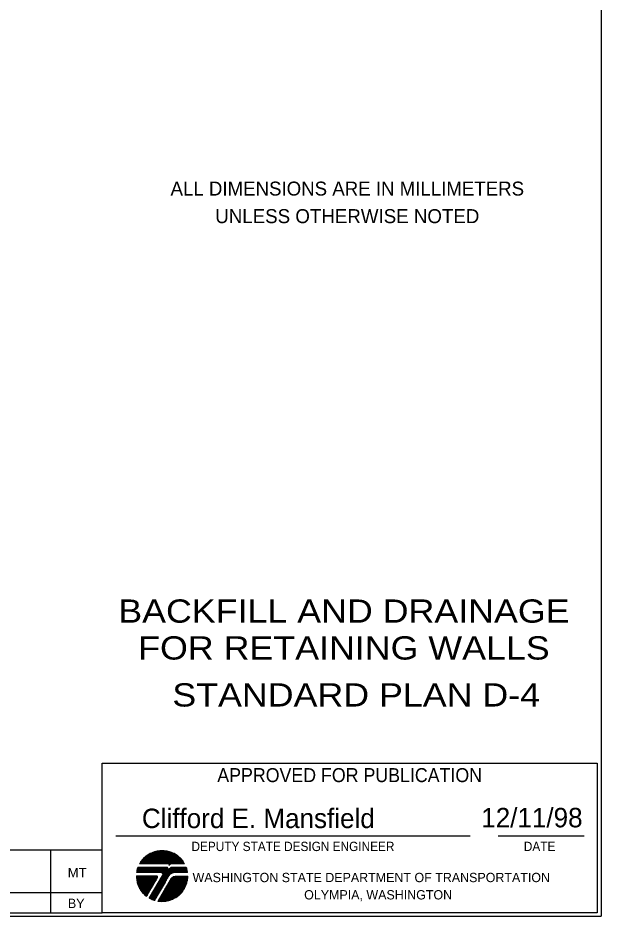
# Model space of a CAD drawing. Extents: x 17672 to 18472, y -9785 to -9267.
# Drawn here: x 18303.8 to 18471.8, y -9784.8 to -9525.9 of the extents above; entities that cross this region are included whole.
import ezdxf
from ezdxf.enums import TextEntityAlignment as Align

# ---------------------------------------------------------------- set-up
doc = ezdxf.new("R2010")
doc.units = 0
doc.header["$LTSCALE"] = 1.4
for name, color, linetype in [('19', 7, 'Continuous'), ('32', 7, 'Continuous'), ('62', 7, 'Continuous')]:
    doc.layers.add(name, color=color, linetype=linetype)
for name, color, linetype, lineweight in [('20', 7, 'Continuous', 25), ('30', 7, 'Continuous', 25), ('63', 7, 'Continuous', 13)]:
    doc.layers.add(name, color=color, linetype=linetype, lineweight=lineweight)

msp = doc.modelspace()

# ---------------------------------------------------------------- linework, layer by layer
at = {"layer": '20'}
for p, q in [((18328.054, -9740.702), (18470.641, -9740.702)), ((18331.951, -9761.602), (18434.072, -9761.602)), ((18442.143, -9761.602), (18466.95, -9761.602)), ((18313.274, -9783.872), (18313.274, -9765.673)), ((18328.054, -9783.872), (18328.054, -9765.673)), ((18175.947, -9777.972), (18328.054, -9777.972)), ((18175.947, -9783.872), (18328.054, -9783.872))]:
    msp.add_line(p, q, dxfattribs=at)
for points in [[(18470.641, -9740.702), (18470.641, -9783.872), (18328.054, -9783.872), (18328.054, -9740.702)], [(18175.947, -9783.872), (18175.947, -9765.673), (18328.054, -9765.673)]]:
    msp.add_lwpolyline(points, dxfattribs=at)
at = {"layer": '30'}
for p in [(18471.773, -9267.105), (17671.774, -9784.752)]:
    msp.add_line(p, (18471.773, -9784.752), dxfattribs=at)
at = {"layer": '63'}
for points in [[(18351.794, -9769.693), (18338.799, -9769.693), (18338.917, -9769.529), (18351.713, -9769.529), (18351.591, -9769.328), (18339.042, -9769.328), (18339.12, -9769.166), (18351.466, -9769.166), (18351.388, -9768.962), (18339.245, -9768.962), (18339.365, -9768.801), (18351.265, -9768.801), (18351.106, -9768.636), (18339.483, -9768.636), (18339.65, -9768.477), (18350.983, -9768.477), (18350.782, -9768.274), (18339.851, -9768.274), (18339.929, -9768.073), (18350.657, -9768.073), (18350.454, -9767.911), (18340.133, -9767.911), (18340.333, -9767.749), (18350.253, -9767.749), (18350.093, -9767.587), (18340.537, -9767.587), (18340.738, -9767.384), (18349.846, -9767.384), (18349.645, -9767.22), (18340.985, -9767.22), (18341.267, -9767.016), (18349.365, -9767.016), (18349.081, -9766.857), (18341.549, -9766.857), (18341.875, -9766.656), (18348.758, -9766.656), (18348.39, -9766.534), (18342.24, -9766.534), (18342.645, -9766.333), (18347.986, -9766.333), (18347.461, -9766.129), (18343.167, -9766.129), (18343.858, -9765.967), (18346.77, -9765.967), (18346.407, -9765.928), (18345.924, -9765.847), (18345.316, -9765.847), (18344.709, -9765.847), (18344.179, -9765.928), (18343.858, -9765.967)], [(18338.917, -9769.529), (18339.042, -9769.328), (18339.12, -9769.166), (18339.245, -9768.962), (18339.365, -9768.801), (18339.483, -9768.636), (18339.65, -9768.477), (18339.851, -9768.274), (18339.929, -9768.073), (18340.133, -9767.911), (18340.333, -9767.749), (18340.537, -9767.587), (18340.738, -9767.384), (18340.985, -9767.22), (18341.267, -9767.016), (18341.549, -9766.857), (18341.875, -9766.656), (18342.24, -9766.534), (18342.645, -9766.333), (18343.167, -9766.129)], [(18346.77, -9765.967), (18347.461, -9766.129), (18347.986, -9766.333), (18348.39, -9766.534), (18348.758, -9766.656), (18349.081, -9766.857), (18349.365, -9767.016), (18349.645, -9767.22), (18349.846, -9767.384), (18350.093, -9767.587), (18350.253, -9767.749), (18350.454, -9767.911), (18350.657, -9768.073), (18350.782, -9768.274), (18350.983, -9768.477), (18351.106, -9768.636), (18351.265, -9768.801), (18351.388, -9768.962), (18351.466, -9769.166), (18351.591, -9769.328), (18351.713, -9769.529), (18351.794, -9769.693)], [(18347.341, -9770.136), (18347.341, -9770.097), (18347.341, -9770.016), (18347.341, -9769.975), (18347.341, -9769.975), (18347.341, -9769.935), (18347.26, -9769.894), (18347.26, -9769.85), (18347.216, -9769.813), (18347.137, -9769.774), (18347.012, -9769.693)], [(18348.15, -9769.693), (18347.824, -9769.774), (18347.137, -9769.774), (18347.216, -9769.813), (18347.704, -9769.813), (18347.581, -9769.894), (18347.26, -9769.894), (18347.341, -9769.935), (18347.503, -9769.935), (18347.461, -9769.975), (18347.341, -9769.975), (18347.341, -9770.016), (18347.419, -9770.016), (18347.341, -9770.136), (18347.341, -9770.136), (18347.26, -9770.178), (18347.341, -9770.136)], [(18347.824, -9769.774), (18347.745, -9769.774), (18347.704, -9769.813), (18347.581, -9769.894), (18347.503, -9769.935), (18347.461, -9769.975), (18347.419, -9770.016)], [(18337.99, -9771.874), (18352.603, -9771.874), (18352.64, -9772.078), (18337.99, -9772.078), (18337.905, -9772.242), (18352.64, -9772.242), (18348.758, -9772.242), (18348.554, -9772.323), (18348.15, -9772.445), (18345.395, -9772.445), (18345.52, -9772.607), (18347.824, -9772.607), (18347.62, -9772.727), (18347.581, -9772.808), (18345.52, -9772.808), (18345.52, -9772.85), (18345.478, -9772.97), (18347.419, -9772.97), (18347.341, -9773.087), (18347.26, -9773.132), (18345.316, -9773.132), (18345.235, -9773.335), (18347.174, -9773.335), (18347.098, -9773.494), (18345.152, -9773.494), (18345.032, -9773.695), (18346.973, -9773.695), (18346.895, -9773.862), (18344.912, -9773.862), (18344.787, -9774.063), (18346.77, -9774.063), (18346.652, -9774.186), (18344.709, -9774.186), (18344.628, -9774.387), (18346.569, -9774.387), (18346.49, -9774.548), (18344.544, -9774.548), (18344.383, -9774.752), (18346.329, -9774.752), (18346.248, -9774.955), (18344.304, -9774.955), (18344.223, -9775.112), (18346.164, -9775.112), (18346.044, -9775.279), (18344.103, -9775.279), (18343.978, -9775.44), (18345.961, -9775.44), (18345.843, -9775.641), (18343.9, -9775.641), (18343.775, -9775.803), (18345.721, -9775.803), (18345.64, -9776.007), (18343.696, -9776.007), (18343.615, -9776.168), (18345.557, -9776.168), (18345.395, -9776.328), (18343.495, -9776.328), (18343.37, -9776.492), (18345.316, -9776.492), (18345.235, -9776.695), (18343.292, -9776.695), (18343.167, -9776.857), (18345.113, -9776.857), (18345.032, -9777.058), (18343.091, -9777.058), (18342.966, -9777.22), (18344.912, -9777.262), (18344.787, -9777.423), (18342.887, -9777.423), (18342.762, -9777.585), (18344.709, -9777.585), (18344.628, -9777.744), (18342.645, -9777.744), (18342.561, -9777.945), (18344.508, -9777.945), (18344.383, -9778.112), (18342.483, -9778.112), (18342.358, -9778.313), (18344.304, -9778.313), (18344.179, -9778.475), (18342.28, -9778.475), (18342.155, -9778.639), (18344.103, -9778.639), (18343.978, -9778.801), (18342.037, -9778.801), (18341.954, -9779.002), (18343.9, -9779.002), (18343.775, -9779.161), (18341.794, -9779.161), (18341.711, -9779.362), (18343.696, -9779.362), (18343.574, -9779.529), (18341.633, -9779.529), (18341.549, -9779.61), (18341.75, -9779.73), (18343.495, -9779.73), (18343.37, -9779.894), (18342.155, -9779.894), (18342.483, -9780.095), (18343.292, -9780.095), (18343.167, -9780.257)], [(18338.309, -9770.661), (18338.27, -9770.825), (18338.233, -9771.029), (18338.152, -9771.19), (18338.108, -9771.391), (18338.066, -9771.553), (18338.03, -9771.757), (18337.99, -9771.874), (18337.99, -9772.078)], [(18338.309, -9770.661), (18346.608, -9770.661), (18346.77, -9770.703), (18346.856, -9770.784), (18346.895, -9770.825), (18338.27, -9770.825), (18338.233, -9771.029), (18347.012, -9771.029), (18347.012, -9771.11), (18347.012, -9771.149), (18347.012, -9771.19), (18338.152, -9771.19), (18338.108, -9771.391), (18347.012, -9771.391), (18346.936, -9771.553), (18338.066, -9771.553), (18338.03, -9771.757), (18352.562, -9771.757), (18352.522, -9771.553), (18346.936, -9771.553), (18347.012, -9771.391), (18352.478, -9771.391), (18352.437, -9771.19), (18347.174, -9771.19), (18347.419, -9771.029), (18352.4, -9770.987), (18352.319, -9770.825), (18347.704, -9770.825), (18347.824, -9770.784), (18347.949, -9770.703), (18348.228, -9770.661), (18352.275, -9770.661), (18352.319, -9770.825)], [(18345.152, -9772.242), (18345.395, -9772.445), (18345.52, -9772.607), (18345.52, -9772.808), (18345.478, -9772.97), (18345.316, -9773.132), (18341.633, -9779.529), (18341.75, -9779.73), (18342.155, -9779.894)], [(18348.15, -9772.445), (18347.949, -9772.526), (18347.824, -9772.607), (18347.581, -9772.808), (18347.419, -9772.97), (18347.26, -9773.132), (18347.174, -9773.335), (18347.098, -9773.494), (18346.973, -9773.695), (18346.895, -9773.862), (18346.77, -9774.063), (18346.652, -9774.186), (18346.569, -9774.387), (18346.49, -9774.548), (18346.329, -9774.752), (18346.248, -9774.955), (18343.167, -9780.298)], [(18346.895, -9770.825), (18346.936, -9770.948), (18347.012, -9771.029), (18347.012, -9771.11), (18347.012, -9771.19), (18347.012, -9771.311), (18347.012, -9771.391)], [(18347.704, -9770.825), (18347.419, -9771.029), (18347.174, -9771.19), (18347.012, -9771.391)], [(18352.64, -9772.242), (18352.64, -9772.078), (18352.603, -9771.874), (18352.562, -9771.757), (18352.522, -9771.553), (18352.478, -9771.391), (18352.437, -9771.19), (18352.4, -9770.987)], [(18337.905, -9773.212), (18343.775, -9773.212), (18343.936, -9773.254), (18343.978, -9773.335), (18344.022, -9773.416), (18337.905, -9773.416), (18337.905, -9773.619), (18344.022, -9773.619), (18343.936, -9773.781), (18337.905, -9773.781), (18337.905, -9773.943), (18343.858, -9773.943), (18343.775, -9774.1), (18337.99, -9774.1), (18337.99, -9774.303), (18343.657, -9774.303), (18343.532, -9774.467), (18338.03, -9774.467), (18338.066, -9774.629), (18343.414, -9774.629), (18343.329, -9774.833), (18338.108, -9774.833), (18338.108, -9774.994), (18343.253, -9774.994), (18343.091, -9775.198), (18338.152, -9775.198), (18338.233, -9775.315), (18343.01, -9775.315), (18342.924, -9775.516), (18338.27, -9775.516), (18338.309, -9775.72), (18342.848, -9775.72), (18342.723, -9775.923), (18338.395, -9775.923), (18338.473, -9776.088), (18342.606, -9776.048), (18342.483, -9776.249), (18338.557, -9776.249), (18338.637, -9776.411), (18342.402, -9776.411), (18342.319, -9776.614), (18338.716, -9776.614), (18338.799, -9776.776), (18342.155, -9776.776), (18342.079, -9776.933), (18338.917, -9776.933), (18339.042, -9777.137), (18341.998, -9777.137), (18341.875, -9777.303), (18339.12, -9777.303), (18339.245, -9777.465), (18341.794, -9777.465), (18341.674, -9777.666), (18339.365, -9777.666), (18339.525, -9777.869), (18341.549, -9777.869), (18341.471, -9778.031), (18339.686, -9778.031), (18339.851, -9778.232), (18341.346, -9778.232), (18341.267, -9778.352), (18340.012, -9778.352), (18340.177, -9778.553), (18341.145, -9778.553), (18341.066, -9778.72), (18340.378, -9778.72), (18340.537, -9778.921), (18340.941, -9778.921), (18340.863, -9779.161), (18340.537, -9778.921)], [(18337.905, -9773.212), (18337.905, -9773.416), (18337.905, -9773.619), (18337.905, -9773.781), (18337.905, -9773.943), (18337.99, -9774.1), (18337.99, -9774.303), (18338.03, -9774.467), (18338.066, -9774.629), (18338.108, -9774.833), (18338.108, -9774.994), (18338.152, -9775.198), (18338.233, -9775.315), (18338.27, -9775.516), (18338.309, -9775.72), (18338.395, -9775.923), (18338.557, -9776.249), (18338.637, -9776.411), (18338.716, -9776.614), (18338.799, -9776.776), (18338.917, -9776.933), (18339.042, -9777.137), (18339.12, -9777.303), (18339.245, -9777.465), (18339.365, -9777.666), (18339.525, -9777.869), (18339.686, -9778.031), (18339.851, -9778.232), (18340.012, -9778.352), (18340.177, -9778.553), (18340.378, -9778.72), (18340.537, -9778.921), (18340.941, -9778.921), (18341.066, -9778.72), (18341.145, -9778.553), (18344.022, -9773.619), (18344.022, -9773.494), (18344.022, -9773.416)], [(18352.682, -9773.254), (18352.682, -9773.416), (18352.682, -9773.619), (18352.682, -9773.781), (18352.682, -9773.943), (18352.64, -9774.144), (18352.603, -9774.347), (18352.603, -9774.467), (18352.562, -9774.629), (18352.522, -9774.833), (18352.478, -9775.036), (18352.437, -9775.237), (18352.361, -9775.36), (18352.319, -9775.561), (18352.275, -9775.72), (18352.199, -9775.923), (18352.118, -9776.088), (18352.032, -9776.249), (18351.995, -9776.453), (18351.87, -9776.654), (18351.794, -9776.776), (18351.669, -9776.933), (18351.591, -9777.137), (18351.427, -9777.34), (18351.307, -9777.541), (18351.187, -9777.666), (18351.062, -9777.869), (18350.944, -9778.031), (18350.782, -9778.232), (18350.579, -9778.394), (18350.414, -9778.553), (18350.211, -9778.757), (18350.01, -9778.921), (18349.77, -9779.083), (18349.566, -9779.286), (18349.24, -9779.487), (18348.959, -9779.649), (18348.633, -9779.811), (18348.272, -9779.97), (18347.824, -9780.173), (18347.26, -9780.338), (18346.407, -9780.541), (18344.103, -9780.541), (18344.179, -9780.338), (18347.907, -9773.943), (18348.025, -9773.781), (18348.228, -9773.619), (18348.515, -9773.416)], [(18352.682, -9773.254), (18349.081, -9773.254), (18348.836, -9773.335), (18348.633, -9773.374), (18348.515, -9773.416), (18352.682, -9773.416), (18352.682, -9773.619), (18348.228, -9773.619), (18348.111, -9773.739), (18348.025, -9773.781), (18352.682, -9773.781), (18352.682, -9773.943), (18347.907, -9773.943), (18347.782, -9774.144), (18352.64, -9774.144), (18352.603, -9774.347), (18347.704, -9774.347), (18347.542, -9774.467), (18352.603, -9774.467), (18352.562, -9774.629), (18347.461, -9774.629), (18347.341, -9774.833), (18352.522, -9774.833), (18352.478, -9775.036), (18347.26, -9775.036), (18347.137, -9775.237), (18352.437, -9775.237), (18352.361, -9775.36), (18347.057, -9775.36), (18346.936, -9775.561), (18352.319, -9775.561), (18352.275, -9775.72), (18346.856, -9775.72), (18346.77, -9775.923), (18352.199, -9775.923), (18352.118, -9776.088), (18346.652, -9776.088), (18346.532, -9776.249), (18352.032, -9776.249), (18351.995, -9776.453), (18346.407, -9776.453), (18346.329, -9776.654), (18351.87, -9776.654), (18351.794, -9776.776), (18346.204, -9776.776), (18346.125, -9776.933), (18351.669, -9776.933), (18351.591, -9777.137), (18346, -9777.137), (18345.924, -9777.34), (18351.427, -9777.34), (18351.307, -9777.541), (18345.843, -9777.504), (18345.721, -9777.666), (18351.187, -9777.666), (18351.062, -9777.869), (18345.596, -9777.869), (18345.52, -9778.031), (18350.944, -9778.031), (18350.782, -9778.232), (18345.395, -9778.232), (18345.316, -9778.394), (18350.579, -9778.394), (18350.414, -9778.553), (18345.191, -9778.553), (18345.113, -9778.757), (18350.211, -9778.757), (18350.01, -9778.921), (18344.99, -9778.921), (18344.912, -9779.083), (18349.77, -9779.083), (18349.566, -9779.286), (18344.787, -9779.286), (18344.709, -9779.487)], [(18343.167, -9780.257), (18342.966, -9780.257), (18343.167, -9780.298), (18342.483, -9780.095)], [(18344.709, -9779.487), (18349.24, -9779.487), (18348.959, -9779.649), (18344.584, -9779.61), (18344.508, -9779.811), (18348.633, -9779.811), (18348.272, -9779.97), (18344.383, -9779.97), (18344.304, -9780.173), (18347.824, -9780.173), (18347.503, -9780.298), (18347.26, -9780.338), (18344.179, -9780.338), (18344.103, -9780.541), (18344.103, -9780.541), (18346.407, -9780.541), (18345.961, -9780.578), (18345.277, -9780.622), (18344.628, -9780.578), (18344.103, -9780.541)]]:
    msp.add_lwpolyline(points, dxfattribs=at)

# ---------------------------------------------------------------- texts
at = {"layer": '19'}
for s, height, p in [('ALL DIMENSIONS ARE IN MILLIMETERS', 4.02, (18398.674, -9577.108)), ('UNLESS OTHERWISE NOTED', 4.032, (18398.672, -9585.061))]:
    msp.add_text(s, height=height, dxfattribs=at).set_placement(p, align=Align.CENTER)
at = {"layer": '20'}
for s, height, width, p in [('APPROVED FOR PUBLICATION', 4.032, 0.95, (18399.35, -9746.156)), ('DEPUTY STATE DESIGN ENGINEER', 2.681, 0.95, (18383.012, -9766.026)), ('DATE', 2.681, 0.95, (18454.07, -9766.026)), ('MT', 2.681, 1.05, (18320.84, -9773.565))]:
    msp.add_text(s, height=height, dxfattribs=dict(at, width=width)).set_placement(p, align=Align.CENTER)
for s, p in [('WASHINGTON STATE DEPARTMENT OF TRANSPORTATION', (18405.58, -9774.985)), ('OLYMPIA, WASHINGTON', (18407.558, -9779.972)), ('BY', (18320.573, -9782.443))]:
    msp.add_text(s, height=2.681, dxfattribs=at).set_placement(p, align=Align.CENTER)
at = {"layer": '32', "width": 1.15}
for s, height, p in [('BACKFILL AND DRAINAGE', 6.703, (18397.701, -9700.209)), ('FOR RETAINING WALLS', 6.703, (18397.7, -9710.835)), ('STANDARD PLAN D-4', 6.701, (18401.234, -9724.371))]:
    msp.add_text(s, height=height, dxfattribs=at).set_placement(p, align=Align.CENTER)
at = {"layer": '62'}
for s, p in [('Clifford E. Mansfield', (18373.042, -9759.406)), ('12/11/98', (18451.862, -9759.188))]:
    msp.add_text(s, height=5.607, dxfattribs=at).set_placement(p, align=Align.CENTER)

doc.saveas('drawing.dxf')
